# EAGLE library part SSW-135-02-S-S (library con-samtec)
THROUGH-HOLE .025" SQ POST SOCKET Source: Samtec SSW.pdf
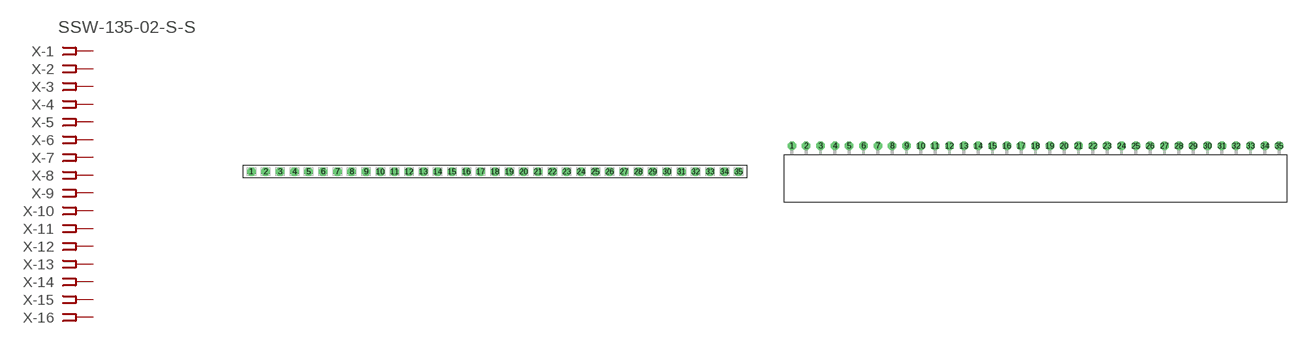
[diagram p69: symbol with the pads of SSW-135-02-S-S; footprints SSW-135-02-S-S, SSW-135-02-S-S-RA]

Designator prefix X; gates -1=FPINV -2=FPIN -3=FPIN -4=FPIN -5=FPIN -6=FPIN -7=FPIN -8=FPIN -9=FPIN -10=FPIN -11=FPIN -12=FPIN -13=FPIN -14=FPIN -15=FPIN -16=FPIN -17=FPIN -18=FPIN -19=FPIN -20=FPIN -21=FPIN -22=FPIN -23=FPIN -24=FPIN -25=FPIN -26=FPIN -27=FPIN -28=FPIN -29=FPIN -30=FPIN -31=FPIN -32=FPIN -33=FPIN -34=FPIN -35=FPIN

## SSW-135-02-S-S (OC_FARNELL: unknown; OC_NEWARK: unknown)  [SSW-135-02-S-S]
1  -1:1  pas
2  -2:1  pas
3  -3:1  pas
4  -4:1  pas
5  -5:1  pas
6  -6:1  pas
7  -7:1  pas
8  -8:1  pas
9  -9:1  pas
10  -10:1  pas
11  -11:1  pas
12  -12:1  pas
13  -13:1  pas
14  -14:1  pas
15  -15:1  pas
16  -16:1  pas
17  -17:1  pas
18  -18:1  pas
19  -19:1  pas
20  -20:1  pas
21  -21:1  pas
22  -22:1  pas
23  -23:1  pas
24  -24:1  pas
25  -25:1  pas
26  -26:1  pas
27  -27:1  pas
28  -28:1  pas
29  -29:1  pas
30  -30:1  pas
31  -31:1  pas
32  -32:1  pas
33  -33:1  pas
34  -34:1  pas
35  -35:1  pas

## SSW-135-02-S-S-RA (OC_FARNELL: unknown; OC_NEWARK: unknown)  [SSW-135-02-S-S-RA]
Pads as for SSW-135-02-S-S

## Footprint SSW-135-02-S-S (pad centres in mm)
THROUGH-HOLE .025" SQ POST SOCKET Source: Samtec SSW.pdf
drill 1 pad 1.5 octagon: 1 -43.18,0; 2 -40.64,0; 3 -38.1,0; 4 -35.56,0; 5 -33.02,0; 6 -30.48,0; 7 -27.94,0; 8 -25.4,0; 9 -22.86,0; 10 -20.32,0; 11 -17.78,0; 12 -15.24,0; 13 -12.7,0; 14 -10.16,0; 15 -7.62,0; 16 -5.08,0; 17 -2.54,0; 18 0,0; 19 2.54,0; 20 5.08,0; 21 7.62,0; 22 10.16,0; 23 12.7,0; 24 15.24,0; 25 17.78,0; 26 20.32,0; 27 22.86,0; 28 25.4,0; 29 27.94,0; 30 30.48,0; 31 33.02,0; 32 35.56,0; 33 38.1,0; 34 40.64,0; 35 43.18,0

## Footprint SSW-135-02-S-S-RA (pad centres in mm)
THROUGH-HOLE .025" SQ POST SOCKET Source: Samtec SSW.pdf
drill 1 pad 1.5 octagon: 1 -43.18,1.524; 2 -40.64,1.524; 3 -38.1,1.524; 4 -35.56,1.524; 5 -33.02,1.524; 6 -30.48,1.524; 7 -27.94,1.524; 8 -25.4,1.524; 9 -22.86,1.524; 10 -20.32,1.524; 11 -17.78,1.524; 12 -15.24,1.524; 13 -12.7,1.524; 14 -10.16,1.524; 15 -7.62,1.524; 16 -5.08,1.524; 17 -2.54,1.524; 18 0,1.524; 19 2.54,1.524; 20 5.08,1.524; 21 7.62,1.524; 22 10.16,1.524; 23 12.7,1.524; 24 15.24,1.524; 25 17.78,1.524; 26 20.32,1.524; 27 22.86,1.524; 28 25.4,1.524; 29 27.94,1.524; 30 30.48,1.524; 31 33.02,1.524; 32 35.56,1.524; 33 38.1,1.524; 34 40.64,1.524; 35 43.18,1.524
